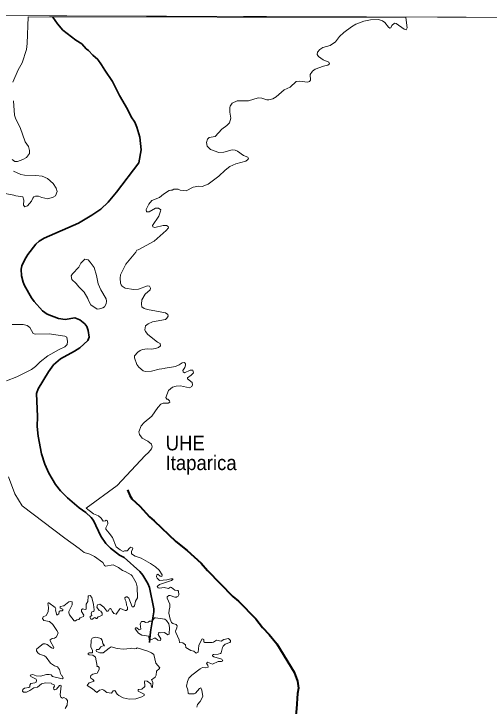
# Model space of a CAD drawing. Extents: x 553962 to 842807, y 8883888 to 9032388.
# Drawn here: x 578434 to 581694, y 8916321 to 8921065 of the extents above; entities that cross this region are included whole.
import ezdxf
from ezdxf.enums import TextEntityAlignment as Align

# ---------------------------------------------------------------- set-up
doc = ezdxf.new("R2010")
doc.units = 0
doc.header["$LTSCALE"] = 150
doc.linetypes.add('LONG_DASH_SHORT_DASH', pattern=[9.9, 6, -1.2, 1.5, -1.2])
doc.layers.add('6', color=7, linetype='Continuous', lineweight=13)

msp = doc.modelspace()

# ---------------------------------------------------------------- linework, layer by layer
at = {"layer": '6'}
for p, q in [((581121.2, 8921038.8), (578531.5, 8921044.3)), ((578490.1, 8917693.2), (578784.8, 8917471.3))]:
    msp.add_line(p, q, dxfattribs=at)
for points in [[(585645.8, 8921027.3), (574684.9, 8921064.7), (574653.9, 8910009.3), (585614.8, 8909969.8)], [(579029.5, 8919174.2), (579068, 8919112.8), (579070.6, 8919095.5), (579066.7, 8919076.9), (579055.5, 8919057.5), (579045.1, 8919049.7), (579021.7, 8919043.2), (579004.8, 8919042.2), (578961.7, 8919069.9), (578946.1, 8919100.1), (578942.2, 8919114.6), (578915.3, 8919158.2), (578879, 8919194.5), (578862, 8919216.2), (578830.6, 8919245.1), (578827.6, 8919270.1), (578835.4, 8919284.4), (578880.7, 8919329.8), (578893.2, 8919356.9), (578920.5, 8919384.2), (578943.8, 8919378.3), (578957.7, 8919364.4), (578984.5, 8919326.4), (579000.5, 8919271), (579011.8, 8919215.7)], [(579311.9, 8916806.7), (579287.8, 8916820.7), (579266.5, 8916850.4), (579268.6, 8916857.6), (579277.9, 8916858.5), (579293.7, 8916844.9), (579306, 8916847.8), (579300.1, 8916885.6), (579310.3, 8916901.8), (579327.1, 8916900.6), (579336.2, 8916894.2), (579354.4, 8916895.9), (579364.9, 8916904.3), (579383.7, 8916903.1), (579397.7, 8916925.9), (579404.7, 8916927.3), (579470, 8916917.5), (579481.4, 8916909), (579497.2, 8916885.2), (579501.4, 8916859.7), (579500.2, 8916815.2), (579490.3, 8916810.1), (579468.2, 8916825.8), (579442.7, 8916822.4), (579430.5, 8916824.9), (579426.2, 8916821), (579424.1, 8916811.8), (579441.9, 8916782), (579440.2, 8916771.4), (579422.4, 8916773.5), (579405, 8916787.9), (579396.9, 8916787.1), (579379.8, 8916776.9), (579361.3, 8916776.1), (579358.7, 8916801.1)], [(579270.4, 8916371.2), (579225.3, 8916369), (579184.5, 8916379.2), (579154.3, 8916394.1), (579141.6, 8916404.3), (579125.9, 8916427.7), (579115.6, 8916426.3), (579102.9, 8916411.1), (579071.1, 8916414.5), (579051.9, 8916431.1), (579041.7, 8916435.3), (579021.4, 8916429.8), (579003.5, 8916415.4), (578973, 8916439.5), (578937.7, 8916461.6), (578938.1, 8916466.8), (578951.7, 8916482), (578984.3, 8916491.4), (578976.3, 8916502.9), (578962.7, 8916513.5), (578958.9, 8916520.8), (578961, 8916530.5), (578976.2, 8916540.7), (579005.2, 8916546.7), (579020.1, 8916573.4), (579018.8, 8916585.7), (579011.2, 8916592.9), (579004, 8916593.8), (579006.5, 8916595.6), (578993.7, 8916657.9), (578975.1, 8916671.1), (578951.3, 8916672.4), (578942.6, 8916676.3), (578943.6, 8916681.1), (578950.8, 8916686.4), (578973.4, 8916685.7), (578972.5, 8916704.2), (578962.8, 8916726.2), (578963.2, 8916774.3), (578972.1, 8916786.7), (578991.6, 8916794.3), (579007.7, 8916792.6), (579030.7, 8916784.1), (579039.2, 8916773.1), (579045.2, 8916751.4), (579055.3, 8916734.4), (579050.6, 8916735.7), (579029.9, 8916727.6), (579017.1, 8916709.4), (579000.2, 8916708.9), (578998, 8916703.4), (579000.5, 8916695.4), (579023, 8916685.6), (579046.8, 8916686.4), (579087.6, 8916719.1), (579102.4, 8916727.1), (579142.9, 8916717), (579187, 8916711.9), (579231.2, 8916715.7), (579238.2, 8916719.5), (579264.4, 8916713.6), (579275.4, 8916715.3), (579279.7, 8916720.4), (579353.2, 8916698.9), (579378.2, 8916687.2), (579394.4, 8916674.1), (579408.8, 8916615.9), (579436, 8916584.4), (579433.8, 8916578.5), (579411.8, 8916560.2), (579409.7, 8916534.3), (579404.1, 8916520.7), (579378.7, 8916502.1), (579386.3, 8916485.9), (579384.2, 8916449.8), (579378.8, 8916451.2), (579372.7, 8916475.2), (579348.1, 8916493.1), (579332, 8916494.3), (579329.4, 8916487.3), (579333.2, 8916463.1), (579331.5, 8916456.5), (579312.8, 8916438.3), (579288.3, 8916435.3), (579285.6, 8916432.2), (579287, 8916424.2), (579328, 8916404), (579327.7, 8916393.3), (579312.8, 8916384.3)]]:
    msp.add_lwpolyline(points, close=True, dxfattribs=at)
for points in [[(574684.9, 8921064.7), (596639.8, 8920989.8), (607636.3, 8920937.2), (626625.7, 8920820.5)], [(578531.5, 8921044.3), (578525.4, 8920861.1), (578521, 8920819.7), (578490.8, 8920729.8), (578464.8, 8920681.3), (578427.7, 8920597.6)], [(579427.7, 8919679.2), (579427.7, 8919679.2), (579440.6, 8919712.7), (579441.1, 8919721), (579426, 8919734), (579406.5, 8919734.1), (579361.6, 8919708.6), (579343.9, 8919709), (579340.8, 8919723.7), (579359.8, 8919759.6), (579380.5, 8919785), (579433.7, 8919806.7), (579461, 8919829.2), (579499, 8919853.4), (579510.9, 8919857.7), (579520.2, 8919857.3), (579532.2, 8919862.4), (579560.4, 8919862.5), (579574.2, 8919857.3), (579615.3, 8919851.7), (579664.7, 8919876.3), (579702.2, 8919884.9), (579725.6, 8919882.8), (579767.1, 8919897.1), (579839.7, 8919952.8), (579883, 8919994.7), (579914.9, 8920018.5), (579956.5, 8920036.3), (580025.6, 8920054.4), (580039.4, 8920065.7), (580043.3, 8920072.7), (580039.4, 8920083), (580010, 8920094.7), (579966.9, 8920124.4), (579951.3, 8920131.8), (579930.5, 8920133.6), (579875.2, 8920117.1), (579840.6, 8920115.8), (579783.6, 8920134.8), (579758.8, 8920158.4), (579754.6, 8920184.2), (579761.9, 8920206.2), (579774.5, 8920217), (579813.8, 8920225.3), (579860.1, 8920275.4), (579895.5, 8920300.4), (579913.9, 8920318.8), (579921.6, 8920350.7), (579915.8, 8920390.8), (579915.4, 8920422), (579918, 8920433.2), (579931, 8920453.1), (579965, 8920468.6), (580042.9, 8920468.2), (580110.4, 8920489.4), (580135, 8920486.7), (580169.2, 8920474.7), (580182.1, 8920474.7), (580209.9, 8920482.9), (580232.8, 8920495.5), (580286.8, 8920543.9), (580330.1, 8920563.4), (580370.3, 8920600.1), (580392.2, 8920604), (580447.8, 8920597.7), (580462.7, 8920600.1), (580468.1, 8920609.3), (580465.4, 8920649.4), (580481.8, 8920671.8), (580500.4, 8920686.3), (580558.2, 8920706.8), (580587.8, 8920713.2), (580598.4, 8920722.8), (580593.6, 8920732.5), (580556.5, 8920749.3), (580522.5, 8920773), (580513.8, 8920785.1), (580515.5, 8920802.9), (580532.8, 8920821), (580553.6, 8920834), (580604.1, 8920848.2), (580639.6, 8920872.9), (580666.9, 8920910.2), (580696.6, 8920937.3), (580749.4, 8920976.7), (580780.5, 8920993.1), (580834, 8921014.6), (580880.7, 8921023.8), (580934, 8921026.4), (580962.9, 8921016.4), (580979.4, 8921004.4), (581002.3, 8920972.3), (581011.8, 8920966.3), (581020.4, 8920969.7), (581025.8, 8920985.4), (581044.8, 8921001.3), (581055.1, 8920999.5), (581110, 8920959.3), (581125.1, 8920955.5), (581132, 8920968.4), (581121.2, 8921038.8)], [(578432.8, 8920469.4), (578439.3, 8920370.1), (578446.7, 8920342.4), (578476.9, 8920285.4), (578512.4, 8920187.2), (578534, 8920155.6), (578541.8, 8920127.9), (578541.8, 8920108.5), (578520.6, 8920080.8), (578496, 8920066.1), (578459.8, 8920053.6), (578441.4, 8920053.6), (578423.4, 8920067.4)], [(578431.9, 8919986.2), (578483, 8919962.8), (578507.1, 8919958.9), (578585.1, 8919958), (578628.8, 8919952.9), (578664.6, 8919935.5), (578704.8, 8919902.2), (578724.3, 8919870.2), (578732, 8919846.5), (578718.7, 8919818.4), (578704.2, 8919807.5), (578668, 8919796.3), (578626, 8919806.2), (578603.8, 8919815), (578582, 8919815.4), (578572.1, 8919811), (578564.3, 8919802.8), (578555.3, 8919780.5), (578527.5, 8919748.3), (578508.6, 8919741.9), (578499.4, 8919754.4), (578502.8, 8919788.5), (578495.9, 8919811.9), (578446.7, 8919817.1), (578434.1, 8919823.1), (578361.1, 8919836.1)], [(579295.8, 8918182.3), (579291.5, 8918200.6), (579307.5, 8918242), (579327.8, 8918264.5), (579381, 8918307.3), (579422.1, 8918366.6), (579442.8, 8918390.3), (579458.5, 8918396.8), (579492.9, 8918398.1), (579504.6, 8918403.3), (579502.1, 8918414), (579491.2, 8918423.6), (579484.3, 8918425.4), (579477, 8918437), (579495.2, 8918484.1), (579521.1, 8918506.1), (579547.4, 8918513.1), (579576, 8918516.1), (579639.6, 8918503.2), (579655.1, 8918511.3), (579659.8, 8918523.3), (579656.9, 8918537.9), (579624.6, 8918563), (579625.6, 8918570.8), (579651.2, 8918588.3), (579665, 8918605.2), (579661.2, 8918622.9), (579642.5, 8918623.8), (579604.2, 8918605.7), (579595.9, 8918611.7), (579593.3, 8918620.7), (579607.5, 8918642.4), (579612.3, 8918657.9), (579611.4, 8918665.7), (579604.8, 8918676.1), (579589, 8918673.1), (579568.6, 8918658.8), (579543.1, 8918648), (579472.5, 8918637.1), (579466.2, 8918633.7), (579429.9, 8918630.3), (579378.4, 8918616.5), (579337.7, 8918613.6), (579320.5, 8918618.6), (579290.7, 8918643.6), (579278.5, 8918662.3), (579260.9, 8918708.6), (579260.8, 8918720.6), (579283.7, 8918747.4), (579301.1, 8918759.1), (579316.6, 8918764.7), (579347.4, 8918769.1), (579377.5, 8918767.2), (579405.6, 8918771.7), (579426.4, 8918779), (579440.6, 8918790.7), (579436.8, 8918806.1), (579419.9, 8918814.4), (579352.2, 8918867.1), (579336.1, 8918887.9), (579332.2, 8918899.6), (579337.8, 8918926.9), (579354.2, 8918939.8), (579384.9, 8918954.1), (579473.2, 8918970.6), (579483.9, 8918978.8), (579491.7, 8918993.8), (579490.8, 8919005.1), (579473.9, 8919017.2), (579350.2, 8919038), (579327.8, 8919045.3), (579311.8, 8919056.6), (579309.2, 8919076.5), (579311, 8919104.1), (579335.2, 8919144.6), (579368, 8919174.6), (579371.9, 8919185.9), (579365.5, 8919198.3), (579349.9, 8919200.1), (579288, 8919178.1), (579254.1, 8919175.1), (579198.1, 8919185.4), (579177.3, 8919199.3), (579170, 8919207.9), (579165.7, 8919220.1), (579163.1, 8919253.7), (579165.9, 8919275.9), (579202, 8919349.7), (579270.7, 8919432.7), (579277.7, 8919446.1), (579286.3, 8919447.9), (579397, 8919507.9), (579478.6, 8919579.2), (579494.3, 8919598.8), (579492.9, 8919608.3), (579480, 8919613.9), (579457.5, 8919613.4), (579401.3, 8919601.8), (579386.2, 8919606.1), (579384.5, 8919613.8), (579427.7, 8919679.2)], [(578421.6, 8918937.2), (578497.7, 8918935.9), (578526.2, 8918930.3), (578544.1, 8918914.6), (578567.3, 8918875.5), (578580.7, 8918869.8), (578675.8, 8918871.9), (578783.4, 8918855.9), (578796.5, 8918849), (578802.1, 8918820.4), (578799.9, 8918799.8), (578784.2, 8918783.7), (578745, 8918765.1), (578668.1, 8918721.9), (578614, 8918680.4), (578582.9, 8918647.6)], [(578582.9, 8918647.6), (578556.1, 8918628.1), (578453.6, 8918577.1), (578384.4, 8918551.1)], [(578930.2, 8917676.9), (579142.2, 8917833.7), (579335.3, 8918038.9), (579357.7, 8918059.2), (579378.4, 8918084.7), (579383.1, 8918098.5), (579378.9, 8918116.6), (579352.9, 8918137.4), (579315, 8918157.6), (579295.8, 8918182.3), (579295.8, 8918182.3)], [(578397.3, 8917891.4), (578441.2, 8917776.7), (578490.1, 8917693.2)], [(579525.2, 8917189.8), (579524.8, 8917193.3), (579511.2, 8917193.8), (579483.6, 8917186.5), (579433, 8917181.8), (579416.5, 8917197.1), (579413.1, 8917206.5), (579414.3, 8917221.7), (579420.8, 8917225.1), (579438.1, 8917211.1), (579449.9, 8917208.6), (579451.7, 8917220), (579429.6, 8917254), (579405.4, 8917276.1), (579372.3, 8917299.4), (579307.2, 8917334.8), (579266.1, 8917349.2), (579241.9, 8917365.8), (579241.4, 8917382.3), (579249.1, 8917398.6), (579247.4, 8917406.9), (579236.3, 8917410.3), (579228.6, 8917406.1), (579211.6, 8917386.2), (579192.2, 8917386.1), (579184.8, 8917381.9), (579163.3, 8917391.7), (579134.8, 8917412.9), (579109.7, 8917475.8), (579088.5, 8917506.3), (579064.7, 8917532.7), (579065.9, 8917544.1), (579078.3, 8917570.1), (579077, 8917590.1), (579067.2, 8917595.1), (579063.4, 8917591.8), (579047.7, 8917589.2), (579032.8, 8917608.4), (579014.6, 8917624.9), (578981, 8917639.3), (578930.2, 8917676.9)], [(578784.8, 8917471.3), (578882.4, 8917401), (578916, 8917372.9), (578955.9, 8917361.9), (578987.8, 8917346.2), (579044.3, 8917305.4), (579055.8, 8917285.8), (579063, 8917280.4), (579114.1, 8917288.8), (579152.6, 8917271.4), (579179.4, 8917250.6), (579196.4, 8917244.7), (579238.8, 8917221.3), (579246.1, 8917213.2)], [(579246.1, 8917213.2), (579272, 8917166.4), (579278.8, 8917138.4), (579283, 8917063.6), (579268.4, 8917041), (579260.5, 8917007.6), (579254.2, 8917001.7), (579246.1, 8917002.5), (579223.2, 8917060.3), (579211.7, 8917070.4), (579204, 8917070.4), (579196, 8917062.4), (579196.4, 8917050.1), (579203.6, 8917036.1), (579206.6, 8917012.7), (579214.2, 8916998.7), (579214.2, 8916983.4), (579204, 8916976.3), (579197.2, 8916976.2), (579166.3, 8916989.7), (579160.8, 8916988.5), (579136.9, 8916951.5), (579120, 8916957.1), (579108.5, 8916971.1), (579101.6, 8916985.6), (579094.5, 8916990.2), (579089.8, 8916988), (579081.2, 8916971.9), (579072.7, 8916971.9), (579051.9, 8916999.1), (579024, 8917020.7), (579007.3, 8917014.4), (579003.5, 8917000.4), (579019, 8916977.3), (579019, 8916977.3), (579030.7, 8916971.9), (579040.8, 8916958.5), (579038.9, 8916945.5), (579025.6, 8916936.7), (579012, 8916934.1), (579004.3, 8916920.9), (578998.8, 8916921), (578989.1, 8916928.1), (578980.6, 8916924.7), (578972.7, 8916916.7), (578963.1, 8916917.2), (578957.6, 8916929.5), (578958.5, 8916934.5), (578969.1, 8916941.3), (578963.6, 8916954), (578969.1, 8916966.4), (578983.1, 8916969.8), (578986, 8916980.2), (578981, 8917017.8), (578967.8, 8917064.5), (578956.4, 8917078.9), (578945.3, 8917078.1), (578942.8, 8917074.6), (578941.5, 8917037.3), (578930.4, 8917019.4), (578929.2, 8916985.1), (578923.6, 8916982.5), (578905.8, 8916987.2), (578896.9, 8916981.2), (578897.3, 8916969.3), (578913.4, 8916943.5), (578912.2, 8916936.2), (578889.4, 8916926.1), (578879, 8916915.4), (578866.7, 8916912.8), (578856.5, 8916906.5), (578847.2, 8916906.5), (578816.6, 8916946), (578811.5, 8916960), (578811.5, 8916969.4), (578834, 8917016.1), (578833.1, 8917036.5), (578819.2, 8917038.6), (578810.7, 8917035.7), (578777.5, 8917009.3), (578751.2, 8917003.3), (578751.6, 8916991.5), (578769.8, 8916985.5), (578770.7, 8916979.1), (578766.4, 8916974.9), (578752, 8916974), (578744.8, 8916969.8), (578741.8, 8916953.2), (578730, 8916945.6), (578720.6, 8916978.7), (578722.7, 8916988.1), (578716.3, 8916997.3), (578675.1, 8917029.7), (578669.6, 8917029.7), (578666.2, 8917024.5), (578671.7, 8916996.7), (578668.7, 8916968.5), (578654.6, 8916942.9), (578635.1, 8916932.4), (578630.7, 8916922.7), (578631.7, 8916921.2)], [(579552, 8917069.7), (579561.3, 8917075.6), (579564.7, 8917085), (579564.3, 8917109.5), (579559.6, 8917112.9), (579537.1, 8917115.1), (579515.7, 8917134.7), (579509.1, 8917135.9), (579494.6, 8917128.3), (579464.1, 8917135), (579433.4, 8917128.7), (579423.3, 8917131.2), (579417.3, 8917140.9), (579417.3, 8917140.9), (579433.5, 8917154.2), (579514.2, 8917181.8), (579525.2, 8917189.5), (579525.2, 8917189.8)], [(579917.7, 8916773.9), (579905.3, 8916783.7), (579873.7, 8916777.8), (579854.9, 8916765.9), (579824.3, 8916772.2), (579804, 8916759.5), (579793.8, 8916756.9), (579742.8, 8916758.2), (579736, 8916760.8), (579735.9, 8916777.3), (579728.7, 8916781.6), (579722.4, 8916779.5), (579702.8, 8916736.5), (579697.3, 8916690.3), (579683.4, 8916685.2), (579668, 8916698.3), (579647.1, 8916703.6), (579614.5, 8916722.5), (579612.3, 8916740.7), (579594.1, 8916756.1), (579569, 8916757.4), (579566.8, 8916774.8), (579544.4, 8916825.7), (579542.7, 8916835.9), (579552.8, 8916857.2), (579555, 8916872.1), (579547.3, 8916880.6), (579523.5, 8916886.6), (579516.3, 8916894.6), (579507, 8916917.5), (579497.6, 8916958.4), (579498.9, 8916978.7), (579504.8, 8916999.2), (579504.8, 8917019.4), (579485.3, 8917060.5), (579485.3, 8917070.5), (579497.2, 8917078.5), (579506.5, 8917079.8), (579537.1, 8917068.4), (579549.4, 8917068), (579552, 8917069.7)], [(578631.7, 8916921.2), (578640.3, 8916907.8), (578679.7, 8916902.2), (578702.3, 8916880.2), (578729.5, 8916840.6), (578737.5, 8916822.4), (578726.5, 8916796.5), (578712.9, 8916787.1), (578697.6, 8916783.7), (578683.2, 8916775.6), (578682.8, 8916767.8), (578707.8, 8916723.8), (578705.3, 8916715.8), (578692.9, 8916720.8), (578663.6, 8916743.8), (578648.3, 8916748.4), (578635.2, 8916748), (578592.7, 8916714.5), (578589.3, 8916708.7)], [(579864.7, 8916634.6), (579861.4, 8916642.2), (579805, 8916658.7), (579796.7, 8916665.6), (579795.9, 8916670.7), (579803.2, 8916676.2), (579835.4, 8916676.7), (579851.1, 8916681.8), (579855.3, 8916686.5), (579864.7, 8916722.1), (579870.6, 8916733.1), (579883.4, 8916745), (579914.8, 8916756.9), (579919.9, 8916762.5), (579919.4, 8916772.6), (579917.7, 8916773.9)], [(578589.3, 8916708.7), (578588.8, 8916707.7), (578589.3, 8916700.1), (578598.2, 8916685.6), (578609.3, 8916678.3), (578645.4, 8916665.1), (578655.6, 8916655.8), (578686.2, 8916614.6), (578713.8, 8916596.8), (578734.5, 8916590), (578747.8, 8916573.3), (578753.7, 8916545.4), (578761.3, 8916530.1), (578765.6, 8916528.3), (578771.5, 8916511.8), (578766.4, 8916508.4), (578700.2, 8916523.2), (578689.5, 8916535.2), (578675.5, 8916539), (578675.5, 8916539), (578658.5, 8916539), (578615.9, 8916527.1), (578588, 8916528.8), (578564.2, 8916539), (578546, 8916533.9), (578550.2, 8916525.4), (578586.3, 8916505), (578590.1, 8916497.7), (578586.8, 8916486.4), (578577, 8916480.4), (578551.1, 8916476.1), (578544.7, 8916463.9), (578543.9, 8916454.1), (578536.1, 8916449.8), (578507.3, 8916444.7), (578497.4, 8916436.8)], [(579688.3, 8916313.8), (579694.3, 8916332.9), (579711.3, 8916352.4), (579729.1, 8916387.4), (579724.1, 8916431.5), (579716.4, 8916446.8), (579706.2, 8916443), (579680.1, 8916410.7), (579669.6, 8916406.4), (579636.5, 8916405.2), (579628.5, 8916410.7), (579627.6, 8916434), (579617.4, 8916457.2), (579624.2, 8916490.1), (579634.7, 8916512), (579654.4, 8916533.9), (579711.3, 8916577.2), (579727.5, 8916585.3), (579746.2, 8916584), (579767.8, 8916589.2), (579764.8, 8916601.4), (579755.1, 8916613.3), (579762.7, 8916622.2), (579796.7, 8916609.9), (579834.5, 8916626.9), (579859, 8916627.8), (579866.2, 8916631.2), (579864.7, 8916634.6)], [(578497.4, 8916436.8), (578495.8, 8916435.5), (578492.9, 8916423), (578500.7, 8916416.6), (578520.1, 8916417.9), (578544.7, 8916429), (578570.2, 8916446.4), (578597, 8916452.3), (578624.6, 8916474.4), (578650.8, 8916481.6), (578690.3, 8916479.5), (578692.6, 8916473.2), (578709.5, 8916467.6), (578713.8, 8916458.7), (578706.1, 8916446.7), (578707.4, 8916437), (578712.1, 8916431.9), (578727.3, 8916437.9), (578746.9, 8916462.5), (578756.1, 8916465.1), (578758.8, 8916459.5), (578752.4, 8916399.3), (578756.2, 8916382.7), (578768, 8916375.9), (578776.2, 8916379.7), (578793.6, 8916372), (578801.3, 8916359.2), (578800.4, 8916328.4), (578786.4, 8916304)]]:
    msp.add_lwpolyline(points, dxfattribs=at)
at = {"layer": '6', "linetype": 'LONG_DASH_SHORT_DASH', "lineweight": 35}
msp.add_lwpolyline([(578702.1, 8921041.7), (578732.5, 8920996.5), (578770, 8920953.4), (578860.1, 8920883.7), (578900.2, 8920859.1), (578930.9, 8920824.9), (578945.6, 8920814.5), (578976.3, 8920780.8), (579009.1, 8920751.4), (579036, 8920715.1), (579057.2, 8920678.8), (579111.6, 8920601.8), (579159.6, 8920505), (579214.2, 8920410.6), (579239.6, 8920358), (579263.4, 8920321.7), (579278.1, 8920289.2), (579298, 8920220.5), (579306.6, 8920132.3), (579291, 8920043.1), (579137.8, 8919842.8), (579080.5, 8919775.2), (579029.5, 8919725.5), (578969.8, 8919684.3), (578878.2, 8919631.6), (578641.2, 8919527.8), (578607.5, 8919506.6), (578585.5, 8919485.5), (578531, 8919416.2), (578508.9, 8919382.5), (578489.1, 8919337.6), (578485.2, 8919315.1), (578487.3, 8919270.2), (578498.6, 8919225.2), (578508.1, 8919202.8), (578554.8, 8919118), (578572.9, 8919093.8), (578630.4, 8919030.2), (578662.2, 8919005.9), (578740.7, 8918978.3), (578785.6, 8918971), (578853, 8918981.3), (578886.8, 8918967.1), (578920.4, 8918940.8), (578934.7, 8918922.2), (578944.3, 8918894), (578949.9, 8918849), (578940.4, 8918826.6), (578886.4, 8918777.3), (578850.5, 8918753.1), (578753.6, 8918701.1), (578706.1, 8918660.5), (578672.4, 8918612.1), (578601.1, 8918496.3), (578590.2, 8918462.5), (578595.4, 8918305.1), (578594.6, 8918237.6), (578601, 8918170.3), (578622.6, 8918051), (578647.7, 8917978.3), (578674.1, 8917918.6), (578719.9, 8917840.4), (578754.5, 8917795.8), (578802.9, 8917748.3), (578882.1, 8917679.1), (578927.3, 8917649), (578965.1, 8917614.7), (578979.8, 8917594.3), (579031.7, 8917485.4), (579064.8, 8917435.4), (579097.3, 8917404.1), (579157.9, 8917356.5), (579191.2, 8917339.2), (579297.6, 8917243.3), (579319.2, 8917218.6), (579353.8, 8917162), (579364.1, 8917134.3), (579394.4, 8916988.5), (579393.5, 8916968.2), (579370.6, 8916829.9), (579363.6, 8916758.3)], dxfattribs=at)
at = {"layer": '6', "lineweight": 40}
msp.add_lwpolyline([(579213.9, 8917803.6), (579228.4, 8917763.4), (579242.2, 8917742.7), (579298.8, 8917690.5), (579364.6, 8917617.7), (579396.1, 8917591.3), (579545.7, 8917448.6), (579623.5, 8917387.3), (579718.5, 8917299.9), (579761.2, 8917250.1), (579934.8, 8917073.4), (579974.1, 8917041), (580094.4, 8916919), (580138.8, 8916860.8), (580185.2, 8916812.2), (580237.9, 8916747.8), (580356.4, 8916554.1), (580378.4, 8916492), (580386.2, 8916445.1), (580380.2, 8916408), (580372.4, 8916302.5), (580354.2, 8916132.1), (580354.2, 8916028.7)], dxfattribs=at)

# ---------------------------------------------------------------- texts
at = {"layer": '6', "width": 0.95}
for s, p in [('UHE', (579609.2, 8918073.7)), ('Itaparica', (579718.2, 8917938.5))]:
    msp.add_text(s, height=100, dxfattribs=at).set_placement(p, align=Align.CENTER)

doc.saveas('drawing.dxf')
